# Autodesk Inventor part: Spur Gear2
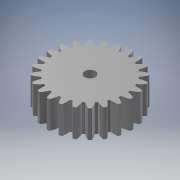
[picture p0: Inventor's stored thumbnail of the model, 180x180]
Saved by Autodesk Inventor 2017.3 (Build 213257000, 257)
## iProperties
Created: 2020-03
Part Number: Spur Gear2
Material: Steel
Document SubType Name: Modeling
Designer: Tim_G
Categories: <?xml version="1.0" encoding="UTF-16"?> <MemberInstance><Categories><FamilyTemplate><FamilyTemplateParameter ValueType="xs:double" Id="1" ObjectReferenceKey="da
Density: 1 g/cm^3
Appearance: Steel
CustomPartVersion: 1
Author: Tim_G
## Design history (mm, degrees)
sketch "Sketch1"
  geometry: C1 r 19.798 at (0, 0)
  constraints: 1 centre point
  dimensions: "d0" = 39.59633 diameter of C1 (= da_da)
extrude "Extrusion1" new body sketch "Sketch1" distance "d1" = 13 (= da_b); taper "d2" = 0 deg
workplane "Work Plane2"
sketch "Sketch2"
  geometry: C1 r 19.798 at (0, 0) reference; C2 r 18.275 at (0, 0)
  constraints: 1 centre point, 1 coincident
  dimensions: "d3" = 36.55046 diameter of C2 (= da_dw)
feature "Pitch Diameter" sketch "Sketch2" dims "d4" = 10, "d5" = 0
workplane "Work Plane8"
workplane "Work Plane9"
feature "Spur Gear" dims "d4" = 10, "da_b" = 13, "da_d" = 36.55046, "da_aw" = 27.41284, "da_da" = 39.59633, "da_df" = 32.74312, "da_dw" = 36.55046, angle "da_beta" = 0 deg, "da_lefttooth" = 0, "da_righttooth" = 0
sketch "Sketch3"
  geometry: C1 r 2.5 at (0, 0); 1 further point
  constraints: 1 centre point, 1 coincident
  dimensions: "d49" = 5 diameter of C1
extrude "Extrusion2" cut sketch "Sketch3" distance "d50" = 13; taper "d51" = 0 deg
body "Solid1"
body "Srf1"
other parameters: "d16" = 27.41284 (= da_aw), "d17" = 0, "d34" = 7.5 deg (computed from da_z), "d39" = 0, "d41" = 0, "d43" = 27.41284 (= da_aw), "d46" = 27.41284 (= da_aw), "d47" = 0, "d48" = 0
